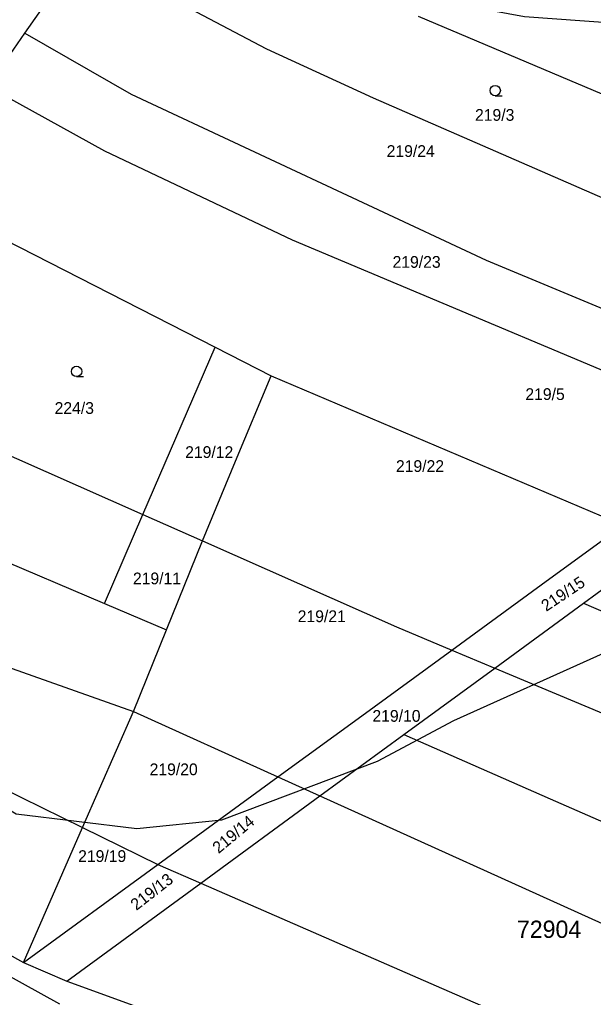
# Model space of a CAD drawing. Extents: x -743888 to -742027, y -1128394 to -1126768.
# Drawn here: x -742998.5 to -742915.5, y -1127789.2 to -1127647.7 of the extents above; entities that cross this region are included whole.
import ezdxf

# ---------------------------------------------------------------- set-up
doc = ezdxf.new("R2010")
doc.units = 0
for name, color, linetype in [('Vrstva 1', 7, 'Continuous'), ('Vrstva 18', 7, 'Continuous'), ('Vrstva 25', 7, 'Continuous'), ('Vrstva 4', 7, 'Continuous'), ('Vrstva 52', 7, 'Continuous'), ('Vrstva 53', 7, 'Continuous'), ('Vrstva 6', 7, 'Continuous')]:
    doc.layers.add(name, color=color, linetype=linetype)

msp = doc.modelspace()

# ---------------------------------------------------------------- linework, layer by layer
at = {"layer": 'Vrstva 1'}
for points in [[(-742997.69, -1127649.67), (-742989.43, -1127637.82)], [(-742989.43, -1127637.82), (-742962.79, -1127651.94)], [(-742940.86, -1127647.2), (-742894.92, -1127666.66)], [(-743003.07, -1127657.38), (-742997.69, -1127649.67)], [(-742962.79, -1127651.94), (-742947.37, -1127659.01)], [(-742947.37, -1127659.01), (-742888.66, -1127684.65)], [(-743013.81, -1127672.8), (-742970.18, -1127695.1)], [(-742970.18, -1127695.1), (-742962.09, -1127699.23)], [(-742967.23, -1127711.61), (-742962.09, -1127699.23)], [(-743013, -1127704.97), (-742980.63, -1127719.3)], [(-742972.01, -1127723.11), (-742967.23, -1127711.61)], [(-743019.3, -1127718.08), (-742986.19, -1127732.18)], [(-742980.63, -1127719.3), (-742972.01, -1127723.11)], [(-742923.05, -1127729.5), (-742911.19, -1127720.85)], [(-742977.22, -1127736), (-742972.01, -1127723.11)], [(-742916.95, -1127732.14), (-742905.07, -1127723.45)], [(-742935.96, -1127738.92), (-742923.05, -1127729.5)], [(-742986.19, -1127732.18), (-742977.22, -1127736)], [(-742929.76, -1127741.52), (-742916.95, -1127732.14)], [(-742982, -1127747.83), (-742977.22, -1127736)], [(-742949.01, -1127748.44), (-742935.96, -1127738.92)], [(-743000.34, -1127741.31), (-742982, -1127747.83)], [(-742942.9, -1127751.14), (-742929.76, -1127741.52)], [(-742989.35, -1127764.58), (-742982, -1127747.83)], [(-742961.12, -1127757.28), (-742949.01, -1127748.44)], [(-742955.04, -1127760.03), (-742942.9, -1127751.14)], [(-742978.46, -1127769.93), (-742961.12, -1127757.28)], [(-742972.27, -1127772.64), (-742955.04, -1127760.03)], [(-742997.92, -1127784.13), (-742989.35, -1127764.58)], [(-742997.92, -1127784.13), (-742978.46, -1127769.93)], [(-742991.64, -1127786.82), (-742972.27, -1127772.64)], [(-743006.65, -1127779.24), (-742997.92, -1127784.13)], [(-742997.92, -1127784.13), (-742991.64, -1127786.82)], [(-742991.64, -1127786.82), (-742967.48, -1127795.61)]]:
    msp.add_lwpolyline(points, dxfattribs=at)
at = {"layer": 'Vrstva 25'}
for p, q in [((-742929.71, -1127658.72), (-742928.71, -1127658.72)), ((-742990.22, -1127699.35), (-742989.22, -1127699.35))]:
    msp.add_line(p, q, dxfattribs=at)
for centre in [(-742929.71, -1127657.97), (-742990.22, -1127698.6)]:
    msp.add_circle(centre, 0.75, dxfattribs=at)
at = {"layer": 'Vrstva 4'}
msp.add_lwpolyline([(-743008.52, -1127781.37), (-742992.69, -1127790.12)], dxfattribs=at)
at = {"layer": 'Vrstva 52'}
for points in [[(-742999.9, -1127643.94), (-742993.87, -1127644.19), (-742992.56, -1127644.25), (-742988.31, -1127643.88), (-742967.13, -1127645.13), (-742930.19, -1127646.38), (-742925.5, -1127647.25), (-742908.13, -1127648.5), (-742903.88, -1127649.38), (-742871.63, -1127651.5), (-742867.81, -1127651.13), (-742864, -1127652.38), (-742831.75, -1127656.13), (-742820.75, -1127657.5), (-742802.94, -1127658.75), (-742777.06, -1127663), (-742726.13, -1127679.88)], [(-743039.23, -1127734.18), (-743030.31, -1127741.5), (-743008.69, -1127756.75), (-742998.94, -1127762.63), (-742981.5, -1127764.75), (-742969.25, -1127763.5), (-742946.75, -1127755), (-742935.69, -1127749.13), (-742914.06, -1127739.38), (-742905.56, -1127736.38), (-742887.75, -1127733), (-742875.44, -1127732.5), (-742855.5, -1127738.88), (-742848.75, -1127745.25), (-742840.69, -1127757.63), (-742837.69, -1127765.63), (-742836, -1127779.25), (-742838.13, -1127798.75), (-742839.81, -1127808.88), (-742842.81, -1127819.13), (-742849.56, -1127831.75), (-742855.17, -1127839.32)], [(-743039.23, -1127734.18), (-743037.36, -1127739.74), (-743036.47, -1127741.45), (-743030.16, -1127753.57), (-743021.89, -1127765.25), (-743006.65, -1127779.24), (-742997.92, -1127784.13), (-742991.64, -1127786.82), (-742967.48, -1127795.61), (-742902.77, -1127815.89), (-742889.66, -1127821.18), (-742882.56, -1127824.07), (-742864.61, -1127832.85), (-742855.17, -1127839.32)]]:
    msp.add_lwpolyline(points, dxfattribs=at)
at = {"layer": 'Vrstva 6'}
for points in [[(-742997.69, -1127649.67), (-742982.33, -1127658.51)], [(-743003.07, -1127657.38), (-742986.2, -1127666.67)], [(-742982.33, -1127658.51), (-742931.01, -1127682.52)], [(-742986.2, -1127666.67), (-742959.07, -1127679.57)], [(-742959.07, -1127679.57), (-742892.82, -1127707.45)], [(-742931.01, -1127682.52), (-742884.93, -1127701.69)], [(-742980.63, -1127719.3), (-742970.18, -1127695.1)], [(-742962.09, -1127699.23), (-742911.19, -1127720.85)], [(-742986.19, -1127732.18), (-742980.63, -1127719.3)], [(-742972.01, -1127723.11), (-742943.98, -1127735.55)], [(-742916.95, -1127732.14), (-742856.57, -1127758.28)], [(-742943.98, -1127735.55), (-742935.96, -1127738.92)], [(-742935.96, -1127738.92), (-742929.76, -1127741.52)], [(-743036.47, -1127741.45), (-742989.35, -1127764.58)], [(-742929.76, -1127741.52), (-742892.25, -1127757.26)], [(-742982, -1127747.83), (-742961.12, -1127757.28)], [(-742942.9, -1127751.14), (-742921.78, -1127760.46)], [(-742961.12, -1127757.28), (-742955.04, -1127760.03)], [(-742955.04, -1127760.03), (-742912.22, -1127779.41)], [(-742921.78, -1127760.46), (-742847.12, -1127793.15)], [(-742989.35, -1127764.58), (-742978.46, -1127769.93)], [(-742978.46, -1127769.93), (-742972.27, -1127772.64)], [(-742972.27, -1127772.64), (-742833.19, -1127833.4)]]:
    msp.add_lwpolyline(points, dxfattribs=at)

# ---------------------------------------------------------------- texts
at = {"layer": 'Vrstva 18'}
for s, p in [('219/3', (-742932.63, -1127662.34)), ('219/24', (-742945.4, -1127667.57)), ('219/23', (-742944.55, -1127683.61)), ('219/5', (-742925.35, -1127702.74)), ('224/3', (-742993.4, -1127704.75)), ('219/12', (-742974.53, -1127711.13)), ('219/22', (-742944.06, -1127713.15)), ('219/11', (-742982.08, -1127729.41)), ('219/21', (-742958.26, -1127734.88)), ('219/10', (-742947.46, -1127749.3)), ('219/20', (-742979.67, -1127757.03)), ('219/19', (-742990, -1127769.59))]:
    msp.add_text(s, height=1.7, dxfattribs=at).set_placement(p)
for s, rotation, p in [('219/15', 33.6662, (-742922.34, -1127733.41)), ('219/14', 39.6679, (-742969.7, -1127768.45)), ('219/13', 37.8631, (-742981.59, -1127776.69))]:
    msp.add_text(s, height=1.7, rotation=rotation, dxfattribs=at).set_placement(p)
at = {"layer": 'Vrstva 53'}
msp.add_text('72904', height=2.5, dxfattribs=at).set_placement((-742926.57, -1127780.57))

doc.saveas('drawing.dxf')
